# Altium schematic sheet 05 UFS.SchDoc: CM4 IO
size 297 x 209 mm; Page Create Date: March  8, 1995; Page Number: 5; Page Size: A4; Comment: radxa_1010; Page Count: 19; RevCode: V1.10; Doc: 05 UFS; DsnPath: D:\WMS\黄工\[RC126]CM4_IO_V1.10\[RC126]_V1.10\CM4 IO_V1.10.DSN; SchematicName: CM4 IO V1.10; PageName: 05 UFS; PageSize: A4; TopSchematic: True
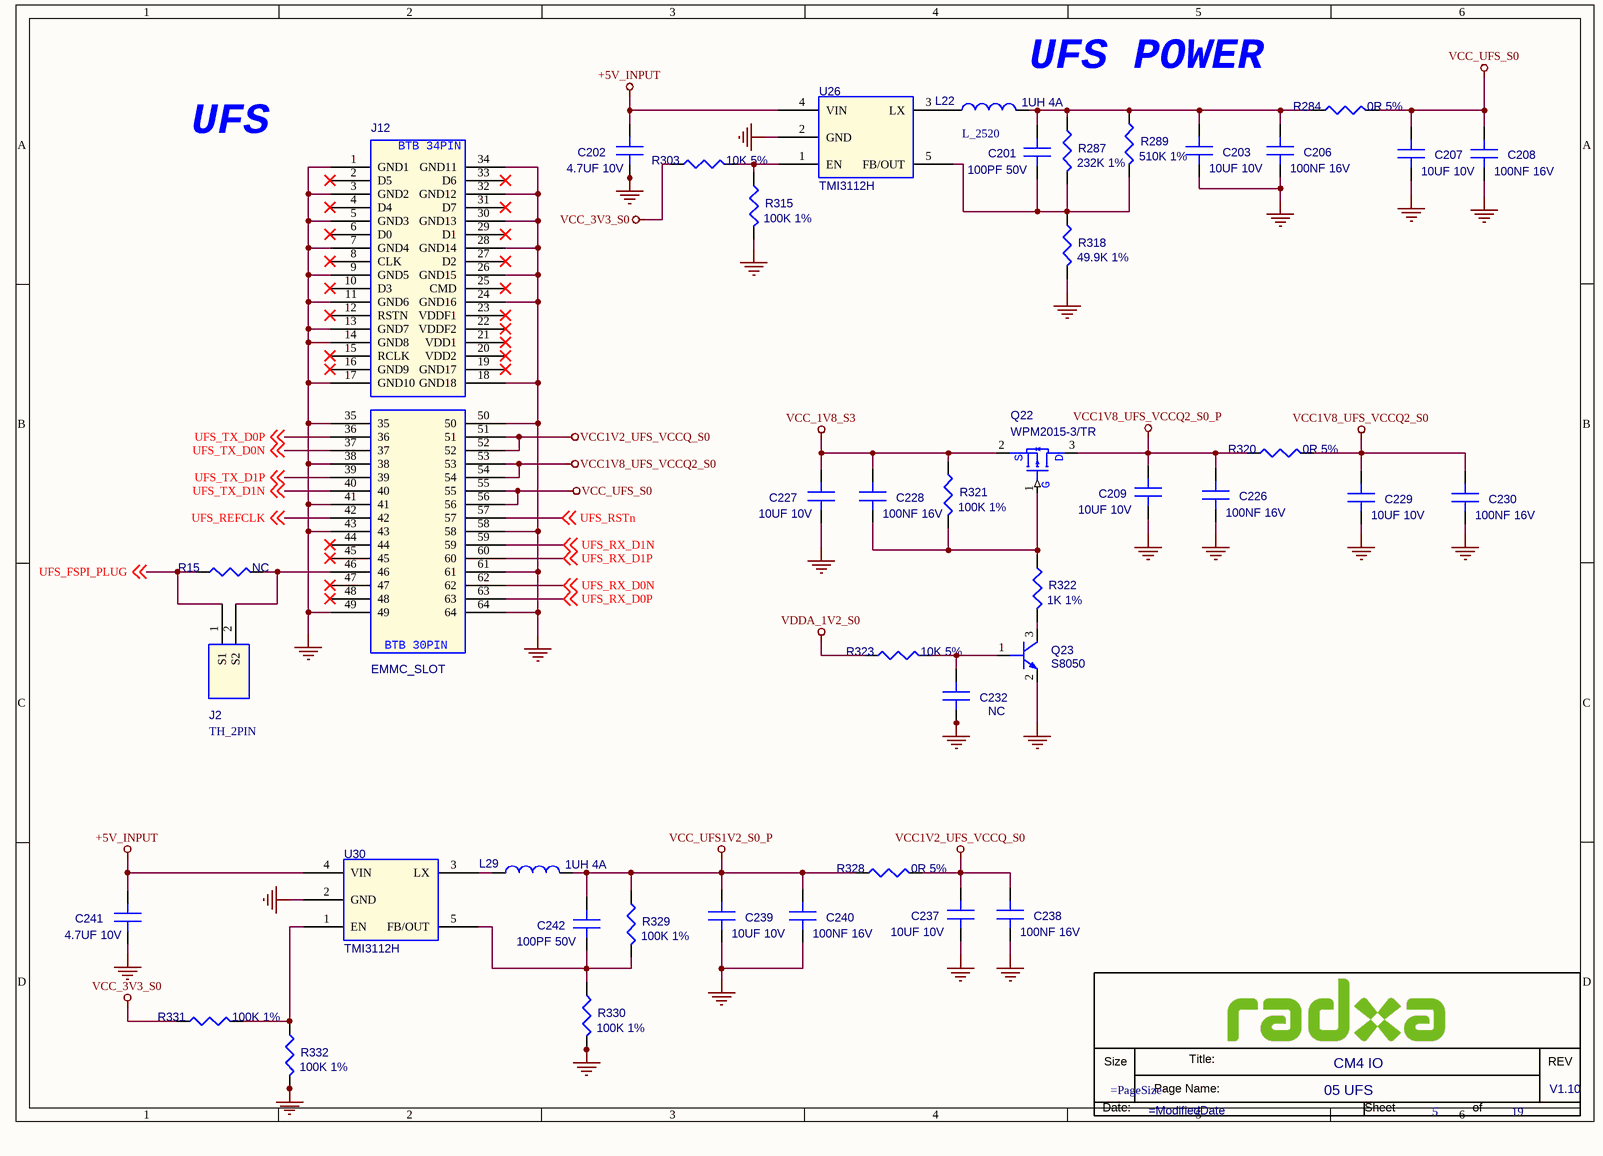
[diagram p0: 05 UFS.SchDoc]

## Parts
*  Doc: 05 UFS  RevCode: V1.10  Title: CM4 IO  Page Number: 5  Page Count: 19  (hidden comment: radxa_1010)  (graphical)
C201  100PF 50V  [C0201]
C202  4.7UF 10V  [C0402]
C203  10UF 10V  [C0402]
C206  100NF 16V  [C0201]
C207  10UF 10V  [C0402]
C208  100NF 16V  [C0201]
C209  10UF 10V  [C0402]
C226  100NF 16V  [C0201]
C227  10UF 10V  [C0402]
C228  100NF 16V  [C0201]
C229  10UF 10V  [C0402]
C230  100NF 16V  [C0201]
C232  NC  [C0201]
C237  10UF 10V  [C0402]
C238  100NF 16V  [C0201]
C239  10UF 10V  [C0402]
C240  100NF 16V  [C0201]
C241  4.7UF 10V  [C0402]
C242  100PF 50V  [C0201]
J2  TH_2PIN  [CON_TH1X2_2D54_STA]
J12  EMMC_SLOT  [EMMC_SLOT_30P_34P]
L22  1UH 4A  [L_2520]
L29  1UH 4A  [L_2520]
Q22  WPM2015-3/TR  [SOT_23]
Q23  S8050  [SOT_23]
R15  NC  [R0402]
R284  0R 5%  [R0402]
R287  232K 1%  [R0402]
R289  510K 1%  [R0402]
R303  10K 5%  [R0402]
R315  100K 1%  [R0402]
R318  49.9K 1%  [R0402]
R320  0R 5%  [R0402]
R321  100K 1%  [R0402]
R322  1K 1%  [R0402]
R323  10K 5%  [R0402]
R328  0R 5%  [R0402]
R329  100K 1%  [R0402]
R330  100K 1%  [R0402]
R331  100K 1%  [R0402]
R332  100K 1%  [R0402]
U26  TMI3112H  [SOT23_5]
U30  TMI3112H  [SOT23_5]

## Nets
+5V_INPUT: C202.1(A) C241.1(A) U26.4(VIN) U30.4(VIN)
GND: C202.2(B) C203.2(B) C206.2(B) C207.2(B) C208.2(B) C209.2(B) C226.2(B) C227.2(B) C229.2(B) C230.2(B) C232.2(B) C237.2(B) C238.2(B) C239.2(B) C240.2(B) C241.2(B) J12.1(GND1) J12.3(GND2) J12.5(GND3) J12.7(GND4) J12.9(GND5) J12.11(GND6) J12.13(GND7) J12.14(GND8) J12.17(GND10) J12.18(GND18) J12.24(GND16) J12.26(GND15) J12.28(GND14) J12.30(GND13) J12.32(GND12) J12.34(GND11) J12.35 J12.38 J12.41 J12.43 J12.49 J12.50 J12.58 J12.61 J12.64 Q23.2(EMITTER) R315.2 R318.2 R330.2 R332.2 U26.2(GND) U30.2(GND)
VCC1V2_UFS_VCCQ_S0: C237.1(A) C238.1(A) J12.51 J12.52 R328.2
VCC1V8_UFS_VCCQ2_S0: C229.1(A) C230.1(A) J12.53 J12.54 R320.2
VCC1V8_UFS_VCCQ2_S0_P: C209.1(A) C226.1(A) Q22.3(D) R320.1
VCC_1V8_S3: C227.1(A) C228.1(A) Q22.2(S) R321.1
VCC_3V3_S0: R303.1 R331.1
VCC_UFS1V2_S0_P: C239.1(A) C240.1(A) C242.1(A) L29.2 R328.1 R329.1
VCC_UFS_S0: C207.1(A) C208.1(A) J12.55 J12.56 R284.2
VDDA_1V2_S0: R323.1
UFS_FSPI_PLUG: J2.1(S1) R15.1 ; off-sheet UFS_FSPI_PLUG
UFS_REFCLK: J12.42 ; off-sheet UFS_REFCLK
UFS_RSTn: J12.57 ; off-sheet UFS_RSTn
UFS_RX_D0N: J12.62 ; off-sheet UFS_RX_D0N
UFS_RX_D0P: J12.63 ; off-sheet UFS_RX_D0P
UFS_RX_D1N: J12.59 ; off-sheet UFS_RX_D1N
UFS_RX_D1P: J12.60 ; off-sheet UFS_RX_D1P
UFS_TX_D0N: J12.37 ; off-sheet UFS_TX_D0N
UFS_TX_D0P: J12.36 ; off-sheet UFS_TX_D0P
UFS_TX_D1N: J12.40 ; off-sheet UFS_TX_D1N
UFS_TX_D1P: J12.39 ; off-sheet UFS_TX_D1P
NetC201_1: C201.1(A) C203.1(A) C206.1(A) L22.2 R284.1 R287.1 R289.1
NetC201_2: C201.2(B) R287.2 R289.2 R318.1 U26.5(FB/OUT)
NetC228_2: C228.2(B) Q22.1(G) R321.2 R322.1
NetC232_1: C232.1(A) Q23.1(BASE) R323.2
NetC242_2: C242.2(B) R329.2 R330.1 U30.5(FB/OUT)
NetJ2_2: J2.2(S2) J12.46 R15.2
NetL22_1: L22.1 U26.3(LX)
NetL29_1: L29.1 U30.3(LX)
NetQ23_3: Q23.3(COLLECTOR) R322.2
NetR303_2: R303.2 R315.1 U26.1(EN)
NetR331_2: R331.2 R332.1 U30.1(EN)

Not connected (* = marked no-connect by the designer): J12 2(D5)* 4(D4)* 6(D0)* 8(CLK)* 10(D3)* 12(RSTN)* 15(RCLK)* 16(GND9)* 19(GND17)* 20(VDD2)* 21(VDD1)* 22(VDDF2)* 23(VDDF1)* 25(CMD)* 27(D2)* 29(D1)* 31(D7)* 33(D6)* 44* 45* 47* 48*

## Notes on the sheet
- UFS POWER
- UFS

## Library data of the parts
C201 = C: SMD  0201  100PF  50V  X5R  ±5%  ROHS; PARTS: 1; Part Reference: C201; Part Number: A1C01.00070; OriginalSymbolOrigin: (0,30); PKG_TYPE: CAP2-100-250; LEVEL: STD; PINSWAP: (A,B)
C202 = C: SMD  0402  4.7UF  10V  X5R  ±20%  ROHS; PARTS: 1; Part Reference: C202; Part Number: A1C01.00073; OriginalSymbolOrigin: (0,30); PKG_TYPE: CAP2-100-250; LEVEL: STD; PINSWAP: (A,B)
C203 = C: SMD  0402  10UF  10V  X5R  ±20%  ROHS; PARTS: 1; Part Reference: C203; Part Number: A1C01.00025; OriginalSymbolOrigin: (0,30); PKG_TYPE: CAP2-100-250; LEVEL: STD; PINSWAP: (A,B)
C206 = C: SMD  0201  100NF  16V  X5R  ±20%  ROHS; PARTS: 1; Part Reference: C206; Part Number: A1C01.00099; OriginalSymbolOrigin: (0,30); PKG_TYPE: CAP2-100-250; LEVEL: STD; PINSWAP: (A,B); Preferred: 6715f349cd0bc5
C207 = C: SMD  0402  10UF  10V  X5R  ±20%  ROHS; PARTS: 1; Part Reference: C207; Part Number: A1C01.00025; OriginalSymbolOrigin: (0,30); PKG_TYPE: CAP2-100-250; LEVEL: STD; PINSWAP: (A,B); Preferred: 6715f349cd0bc5
C208 = C: SMD  0201  100NF  16V  X5R  ±20%  ROHS; PARTS: 1; Part Reference: C208; Part Number: A1C01.00099; OriginalSymbolOrigin: (0,30); PKG_TYPE: CAP2-100-250; LEVEL: STD; PINSWAP: (A,B); Preferred: 6715f349cd0bc5
C209 = C: SMD  0402  10UF  10V  X5R  ±20%  ROHS; PARTS: 1; Part Reference: C209; Part Number: A1C01.00025; OriginalSymbolOrigin: (0,30); PKG_TYPE: CAP2-100-250; LEVEL: STD; PINSWAP: (A,B); Preferred: 6715f349cd0bc5
C226 = C: SMD  0201  100NF  16V  X5R  ±20%  ROHS; PARTS: 1; Part Reference: C226; Part Number: A1C01.00099; OriginalSymbolOrigin: (0,30); PKG_TYPE: CAP2-100-250; LEVEL: STD; PINSWAP: (A,B); Preferred: 6715f349cd0bc5
C227 = C: SMD  0402  10UF  10V  X5R  ±20%  ROHS; PARTS: 1; Part Reference: C227; Part Number: A1C01.00025; OriginalSymbolOrigin: (0,30); PKG_TYPE: CAP2-100-250; LEVEL: STD; PINSWAP: (A,B); Preferred: 6715f349cd0bc5
C228 = C: SMD  0201  100NF  16V  X5R  ±20%  ROHS; PARTS: 1; Part Reference: C228; Part Number: A1C01.00099; OriginalSymbolOrigin: (0,30); PKG_TYPE: CAP2-100-250; LEVEL: STD; PINSWAP: (A,B); Preferred: 6715f349cd0bc5
C229 = C: SMD  0402  10UF  10V  X5R  ±20%  ROHS; PARTS: 1; Part Reference: C229; Part Number: A1C01.00025; OriginalSymbolOrigin: (0,30); PKG_TYPE: CAP2-100-250; LEVEL: STD; PINSWAP: (A,B); Preferred: 6715f349cd0bc5
C230 = C: SMD  0201  100NF  16V  X5R  ±20%  ROHS; PARTS: 1; Part Reference: C230; Part Number: A1C01.00099; OriginalSymbolOrigin: (0,30); PKG_TYPE: CAP2-100-250; LEVEL: STD; PINSWAP: (A,B); Preferred: 6715f349cd0bc5
C232 = C: SMD  0201  100NF  10V  X5R  ±20%  ROHS; PARTS: 1; Part Reference: C232; Part Number: A1C01.00009; OriginalSymbolOrigin: (0,30); PKG_TYPE: CAP2-100-250; LEVEL: STD; PINSWAP: (A,B)
C237 = C: SMD  0402  10UF  10V  X5R  ±20%  ROHS; PARTS: 1; Part Reference: C237; Part Number: A1C01.00025; OriginalSymbolOrigin: (0,30); PKG_TYPE: CAP2-100-250; LEVEL: STD; PINSWAP: (A,B); Preferred: 6715f349cd0bc5
C238 = C: SMD  0201  100NF  16V  X5R  ±20%  ROHS; PARTS: 1; Part Reference: C238; Part Number: A1C01.00099; OriginalSymbolOrigin: (0,30); PKG_TYPE: CAP2-100-250; LEVEL: STD; PINSWAP: (A,B); Preferred: 6715f349cd0bc5
C239 = C: SMD  0402  10UF  10V  X5R  ±20%  ROHS; PARTS: 1; Part Reference: C239; Part Number: A1C01.00025; OriginalSymbolOrigin: (0,30); PKG_TYPE: CAP2-100-250; LEVEL: STD; PINSWAP: (A,B); Preferred: 6715f349cd0bc5
C240 = C: SMD  0201  100NF  16V  X5R  ±20%  ROHS; PARTS: 1; Part Reference: C240; Part Number: A1C01.00099; OriginalSymbolOrigin: (0,30); PKG_TYPE: CAP2-100-250; LEVEL: STD; PINSWAP: (A,B); Preferred: 6715f349cd0bc5
C241 = C: SMD  0402  4.7UF  10V  X5R  ±20%  ROHS; PARTS: 1; Part Reference: C241; Part Number: A1C01.00073; OriginalSymbolOrigin: (0,30); PKG_TYPE: CAP2-100-250; LEVEL: STD; PINSWAP: (A,B)
C242 = C: SMD  0201  100PF  50V  X5R  ±5%  ROHS; PARTS: 1; Part Reference: C242; Part Number: A1C01.00070; OriginalSymbolOrigin: (0,30); PKG_TYPE: CAP2-100-250; LEVEL: STD; PINSWAP: (A,B)
J2 = TH_2PIN: DIP  排针座  1*2PIN  180度  2.54mm脚距  中间朔高2.5mm  针长一端6.1mm  另一端3.0mm  黑色  PH2.54 1*2P L=11.6/3.0  国意英  ROHS; Part Reference: J2; Part Number: A1J02.00011; Temp Coeff: -40°C to +105°C; Preferred: 6715f352cd0bcd; PCB Footprint: CON_TH1X2_2D54_STA_PZ
J12 = EMMC_SLOT: SMD  公座  2*17PIN  180度  8.3*2.7  0.4mm脚距  GB042-34P-H10-E3000  黑色  LG  ROHS; Part Reference: J12; Part Number: A1J01.00030
L22 = L: SMD  带屏蔽  2.5x2x1.2mm  1UH  4A  ±20%  RHP252012T-1R0MT  仁芯微  ROHS; Part Reference: L22; Part Number: A1L01.00117; Preferred: 6715f349cd0bc5; Temp Coeff: -55℃ to +125℃
L29 = L: SMD  带屏蔽  2.5x2x1.2mm  1UH  4A  ±20%  RHP252012T-1R0MT  仁芯微  ROHS; Part Reference: L29; Part Number: A1L01.00117; Preferred: 6715f349cd0bc5; Temp Coeff: -55℃ to +125℃
Q22 = MOSFET_PNP: SMD编带  SOT-23  WPM2015-3/TR  P沟道  ROHS; Part Reference: Q22; Part Number: A1D01.00019; Temp Coeff: -55℃ to ＋150℃
Q23 = NPN: SMD编带  SOT-23  S8050  NPN  ROHS; Part Reference: Q23; Manufacturer PN: S8050_SOT23; Manufacturer: 长电; Part Number: A1D01.00009; Pc: 0.3W; Vceo: 25V; Ic: 0.5A; Priority: A; Temp Coeff: -55℃ to ＋150℃
R15 = R: SMD  0201  0R  1/20W  ±5%  ROHS; Part Reference: R15; Part Number: A1R01.00027; PCB Footprint: R0201; Temp Coeff: －55℃ ~ ＋125℃
R284 = R: SMD  0201  0R  1/20W  ±5%  ROHS; Part Reference: R284; Part Number: A1R01.00027; PCB Footprint: R0201; Temp Coeff: －55℃ ~ ＋125℃
R287 = R: SMD  0201  232K  1/20W  ±1%  ROHS; Part Reference: R287; Part Number: A1R01.00189; PCB Footprint: R0201
R289 = R: SMD  0201  510K  1/20W  ±1%  ROHS; Part Reference: R289; Part Number: A1R01.00460; PCB Footprint: R0201
R303 = R: SMD  0201  10K  1/20W  ±5%  ROHS; Part Reference: R303; Part Number: A1R01.00012; PCB Footprint: R0201; Temp Coeff: －55℃ ~ ＋125℃
R315 = R: SMD  0201  100K  1/20W  ±1%  ROHS; Part Reference: R315; Part Number: A1R01.00165; PCB Footprint: R0201
R318 = R: SMD  0201  49.9K  1/20W  ±1%  ROHS; Part Reference: R318; Part Number: A1R01.00207; PCB Footprint: R0201
R320 = R: SMD  0201  0R  1/20W  ±5%  ROHS; Part Reference: R320; Part Number: A1R01.00027; PCB Footprint: R0201; Temp Coeff: －55℃ ~ ＋125℃
R321 = R: SMD  0201  100K  1/20W  ±1%  ROHS; Part Reference: R321; Part Number: A1R01.00165; PCB Footprint: R0201
R322 = R: SMD  0201  1K  1/20W  ±1%  ROHS; Part Reference: R322; Part Number: A1R01.00111; PCB Footprint: R0201
R323 = R: SMD  0201  10K  1/20W  ±5%  ROHS; Part Reference: R323; Part Number: A1R01.00012; PCB Footprint: R0201; Temp Coeff: －55℃ ~ ＋125℃
R328 = R: SMD  0201  0R  1/20W  ±5%  ROHS; Part Reference: R328; Part Number: A1R01.00027; PCB Footprint: R0201; Temp Coeff: －55℃ ~ ＋125℃
R329 = R: SMD  0201  100K  1/20W  ±1%  ROHS; Part Reference: R329; Part Number: A1R01.00165; PCB Footprint: R0201
R330 = R: SMD  0201  100K  1/20W  ±1%  ROHS; Part Reference: R330; Part Number: A1R01.00165; PCB Footprint: R0201
R331 = R: SMD  0201  100K  1/20W  ±1%  ROHS; Part Reference: R331; Part Number: A1R01.00165; PCB Footprint: R0201
R332 = R: SMD  0201  100K  1/20W  ±1%  ROHS; Part Reference: R332; Part Number: A1R01.00165; PCB Footprint: R0201
U26 = DCDC_ETA3409: SMD  降压转换器  TMI3112H  SOT-23-5  TMI  ROHS; Part Reference: U26; Part Number: A1I01.00618; Manufacturer: TMI(拓尔微电子); Option: /TCS4203; RK PN: 906,000,416; Priority: A
U30 = DCDC_ETA3409: SMD  降压转换器  TMI3112H  SOT-23-5  TMI  ROHS; Part Reference: U30; Manufacturer: TMI(拓尔微电子); Part Number: A1I01.00618; Option: /TCS4203; RK PN: 906,000,416; Priority: A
